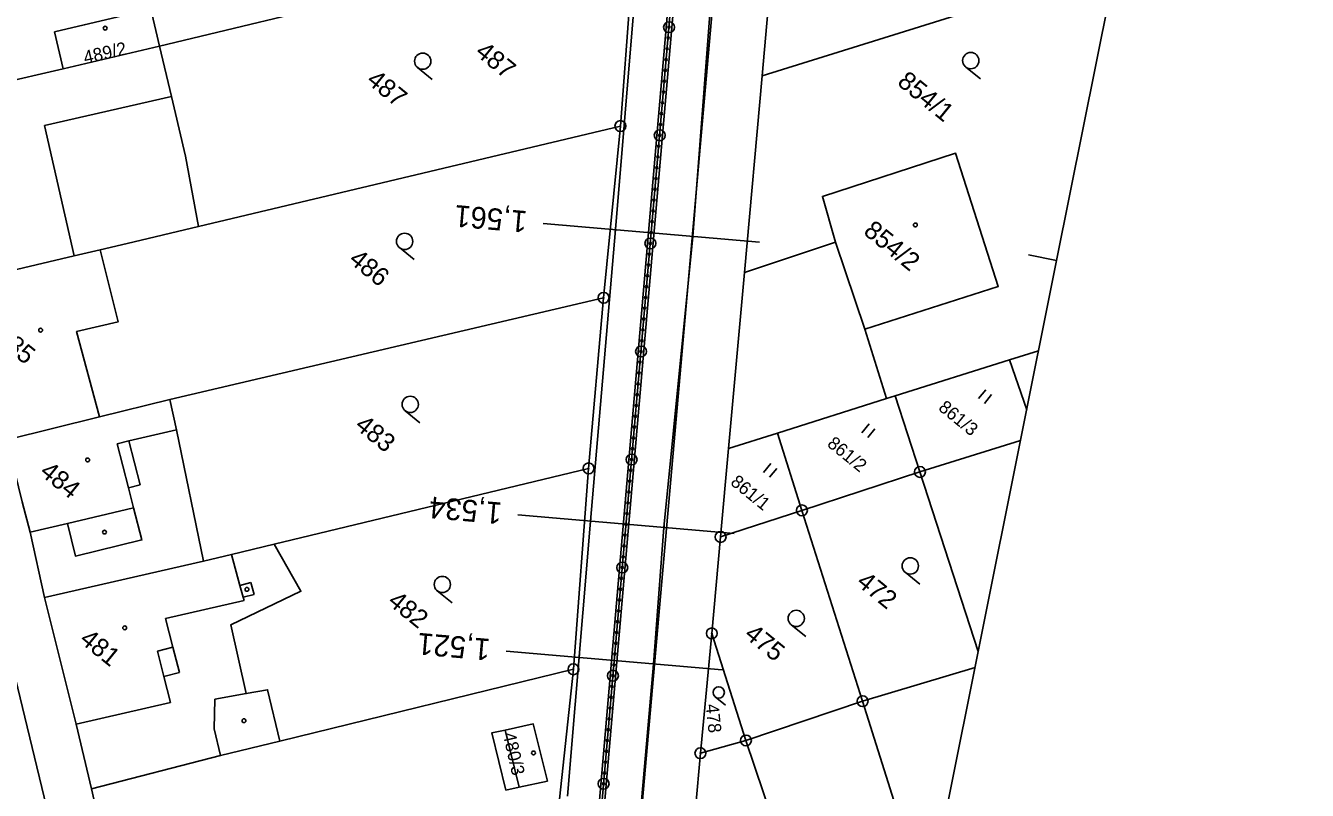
# Model space of a CAD drawing. Extents: x -548552 to -543113, y -1131925 to -1123599.
# Drawn here: x -547952.9 to -547834.8, y -1130256.8 to -1130186.3 of the extents above; entities that cross this region are included whole.
import ezdxf

# ---------------------------------------------------------------- set-up
doc = ezdxf.new("R2010")
doc.units = 0
for name, color, linetype in [('Hranice parcel', 7, 'Continuous'), ('Parcelní čísla', 7, 'Continuous'), ('Poz předměty', 7, 'Continuous'), ('Profile', 7, 'Continuous'), ('PROFILY', 7, 'Continuous'), ('STANIČENÍ', 7, 'Continuous'), ('STANIČENÍ PROFILY', 7, 'Continuous'), ('Vnitřní kresba', 7, 'Continuous'), ('Věcná břemena k části', 7, 'Continuous'), ('Značky bodu BP', 7, 'Continuous'), ('Značky budov', 7, 'Continuous'), ('Značky kultur', 7, 'Continuous')]:
    doc.layers.add(name, color=color, linetype=linetype)

msp = doc.modelspace()

# ---------------------------------------------------------------- linework, layer by layer
at = {"layer": 'Hranice parcel'}
for p, q in [((-547896.75, -1130177.64), (-547940.59, -1130188.23)), ((-547898.11, -1130195.58), (-547896.75, -1130177.64)), ((-547885.05, -1130190.95), (-547884.09, -1130180.24)), ((-547852.46, -1130180.78), (-547885.05, -1130190.95)), ((-547949.45, -1130190.3), (-547950.25, -1130186.89)), ((-547940.59, -1130188.23), (-547949.45, -1130190.3)), ((-547949.45, -1130190.3), (-547962.22, -1130193.28)), ((-547886.69, -1130209.09), (-547885.05, -1130190.95)), ((-547898.11, -1130195.58), (-547936.98, -1130204.83)), ((-547899.66, -1130211.41), (-547898.11, -1130195.58)), ((-547888.14, -1130225.31), (-547886.69, -1130209.09)), ((-547899.66, -1130211.41), (-547939.64, -1130220.79)), ((-547901.04, -1130227.14), (-547899.66, -1130211.41)), ((-547872.78, -1130220.46), (-547862.24, -1130217.13)), ((-547862.24, -1130217.13), (-547859.58, -1130216.29)), ((-547860.67, -1130221.75), (-547862.24, -1130217.13)), ((-547939.64, -1130220.79), (-547946.12, -1130222.39)), ((-547883.63, -1130223.89), (-547873.58, -1130220.71)), ((-547873.58, -1130220.71), (-547872.78, -1130220.46)), ((-547870.51, -1130227.47), (-547872.78, -1130220.46)), ((-547946.12, -1130222.39), (-547954.67, -1130224.5)), ((-547888.14, -1130225.31), (-547883.63, -1130223.89)), ((-547881.38, -1130231.01), (-547883.63, -1130223.89)), ((-547888.14, -1130225.31), (-547888.88, -1130233.46)), ((-547861.24, -1130224.58), (-547870.51, -1130227.47)), ((-547901.04, -1130227.14), (-547930.02, -1130234.13)), ((-547902.44, -1130245.66), (-547901.04, -1130227.14)), ((-547870.51, -1130227.47), (-547881.38, -1130231.01)), ((-547870.51, -1130227.47), (-547865.14, -1130244.03)), ((-547881.38, -1130231.01), (-547888.88, -1130233.46)), ((-547881.38, -1130231.01), (-547875.79, -1130248.6)), ((-547888.88, -1130233.46), (-547889.69, -1130242.35)), ((-547936.53, -1130235.68), (-547951.18, -1130239.03)), ((-547889.69, -1130242.35), (-547890.74, -1130253.39)), ((-547889.69, -1130242.35), (-547886.54, -1130252.22)), ((-547902.44, -1130245.66), (-547929.51, -1130252.29)), ((-547865.43, -1130245.49), (-547875.79, -1130248.6)), ((-547875.79, -1130248.6), (-547886.54, -1130252.22)), ((-547875.79, -1130248.6), (-547870.52, -1130265.27)), ((-547886.54, -1130252.22), (-547890.74, -1130253.39)), ((-547886.54, -1130252.22), (-547880.91, -1130269.02)), ((-547946.86, -1130256.68), (-547936.71, -1130300.6))]:
    msp.add_line(p, q, dxfattribs=at)
for points in [[(-547896.94, -1130267.49), (-547887.74, -1130163.39), (-547881.88, -1130098.3), (-547879.27, -1130068.76), (-547878.13, -1130056.89), (-547878.66, -1130053.71), (-547881.14, -1130041.82), (-547886.59, -1130027.64), (-547894.16, -1130014.15)], [(-547950.25, -1130186.89), (-547947.52, -1130186.26), (-547941.39, -1130184.82), (-547940.59, -1130188.23)], [(-547940.59, -1130188.23), (-547939.49, -1130192.87), (-547939.24, -1130193.91), (-547938.19, -1130198.36), (-547936.98, -1130204.83)], [(-547886.69, -1130209.09), (-547878.28, -1130206.28), (-547879.49, -1130202.06), (-547867.23, -1130198.09), (-547863.29, -1130210.38), (-547875.59, -1130214.31), (-547873.58, -1130220.71)], [(-547936.98, -1130204.83), (-547943.56, -1130206.4), (-547946.04, -1130206.98)], [(-547946.04, -1130206.98), (-547948.46, -1130207.55), (-547958.47, -1130209.9)], [(-547946.12, -1130222.39), (-547948.22, -1130214.53), (-547944.38, -1130213.62), (-547946.04, -1130206.98)], [(-547939.64, -1130220.79), (-547939.02, -1130223.57), (-547936.53, -1130235.68)], [(-547954.67, -1130224.5), (-547953.57, -1130228.83), (-547953.23, -1130230.21), (-547952.52, -1130233.02), (-547951.18, -1130239.03)], [(-547930.02, -1130234.13), (-547933.94, -1130235.09), (-547936.53, -1130235.68)], [(-547929.51, -1130252.29), (-547930.63, -1130247.55), (-547932.59, -1130247.9), (-547934.02, -1130241.56), (-547927.56, -1130238.46), (-547930.02, -1130234.13)], [(-547951.18, -1130239.03), (-547948.27, -1130250.73), (-547946.86, -1130256.68)], [(-547936.71, -1130300.6), (-547917.66, -1130284.08), (-547910.44, -1130275.7), (-547905.63, -1130267.65), (-547903.71, -1130257.64), (-547902.44, -1130245.66)], [(-547908.74, -1130251.26), (-547906.14, -1130250.7), (-547904.84, -1130255.97), (-547907.45, -1130256.53), (-547908.66, -1130256.79), (-547909.95, -1130251.51), (-547908.74, -1130251.26)], [(-547929.51, -1130252.29), (-547934.97, -1130253.6), (-547946.86, -1130256.68)], [(-547890.74, -1130253.39), (-547893.97, -1130289.11), (-547892.39, -1130291.55)]]:
    msp.add_lwpolyline(points, dxfattribs=at)
at = {"layer": 'Poz předměty'}
for p, q in [((-547900.31, -1130260.74), (-547883.44, -1130065.8)), ((-547899.81, -1130260.78), (-547882.94, -1130065.84)), ((-547896.31, -1130177.96), (-547898.56, -1130205.13)), ((-547891.45, -1130205.75), (-547889.36, -1130178.57)), ((-547898.56, -1130205.13), (-547900.86, -1130232.01)), ((-547894.1, -1130232.59), (-547891.45, -1130205.75)), ((-547900.86, -1130232.01), (-547902.99, -1130257.35)), ((-547894.1, -1130232.59), (-547895.07, -1130245.17)), ((-547895.07, -1130245.17), (-547896.46, -1130261.06))]:
    msp.add_line(p, q, dxfattribs=at)
at = {"layer": 'Profile'}
for p, q in [((-547834.8, -1130092.7), (-547857.91, -1130207.98)), ((-547857.91, -1130207.98), (-547881.02, -1130323.27)), ((-547857.91, -1130207.98), (-547860.5, -1130207.46))]:
    msp.add_line(p, q, dxfattribs=at)
at = {"layer": 'PROFILY'}
for points in [[(-547905.23, -1130204.56), (-547885.3, -1130206.28)], [(-547907.56, -1130231.43), (-547887.63, -1130233.15)], [(-547908.64, -1130244), (-547888.72, -1130245.72)]]:
    msp.add_lwpolyline(points, dxfattribs=at)
at = {"layer": 'STANIČENÍ'}
for p, q in [((-547900.06, -1130260.76), (-547883.19, -1130065.82)), ((-547898.58, -1130205.38), (-547898.52, -1130204.73)), ((-547891.5, -1130206.27), (-547891.43, -1130205.5)), ((-547900.89, -1130232.34), (-547900.84, -1130231.76)), ((-547894.11, -1130232.8), (-547894.08, -1130232.44)), ((-547901.95, -1130244.92), (-547901.89, -1130244.24)), ((-547895.1, -1130245.49), (-547895.04, -1130244.76))]:
    msp.add_line(p, q, dxfattribs=at)
for centre, radius in [((-547893.63, -1130186.47), 0.5), ((-547893.63, -1130186.47), 0.1), ((-547893.71, -1130187.47), 0.1), ((-547893.8, -1130188.46), 0.1), ((-547893.89, -1130189.46), 0.1), ((-547894.06, -1130191.45), 0.1), ((-547893.97, -1130190.45), 0.1), ((-547894.14, -1130192.45), 0.1), ((-547894.23, -1130193.44), 0.1), ((-547894.32, -1130194.44), 0.1), ((-547894.49, -1130196.43), 0.5), ((-547894.4, -1130195.44), 0.1), ((-547894.58, -1130197.43), 0.1), ((-547894.49, -1130196.43), 0.1), ((-547894.66, -1130198.42), 0.1), ((-547894.75, -1130199.42), 0.1), ((-547894.83, -1130200.42), 0.1), ((-547894.92, -1130201.41), 0.1), ((-547895.01, -1130202.41), 0.1), ((-547895.18, -1130204.4), 0.1), ((-547895.09, -1130203.41), 0.1), ((-547895.27, -1130205.4), 0.1), ((-547895.35, -1130206.4), 0.5), ((-547895.35, -1130206.4), 0.1), ((-547895.44, -1130207.39), 0.1), ((-547895.52, -1130208.39), 0.1), ((-547895.7, -1130210.38), 0.1), ((-547895.61, -1130209.38), 0.1), ((-547895.78, -1130211.38), 0.1), ((-547895.87, -1130212.37), 0.1), ((-547895.96, -1130213.37), 0.1), ((-547896.04, -1130214.37), 0.1), ((-547896.21, -1130216.36), 0.5), ((-547896.21, -1130216.36), 0.1), ((-547896.13, -1130215.36), 0.1), ((-547896.3, -1130217.35), 0.1), ((-547896.39, -1130218.35), 0.1), ((-547896.47, -1130219.35), 0.1), ((-547896.56, -1130220.34), 0.1), ((-547896.65, -1130221.34), 0.1), ((-547896.82, -1130223.33), 0.1), ((-547896.73, -1130222.34), 0.1), ((-547896.9, -1130224.33), 0.1), ((-547896.99, -1130225.32), 0.1), ((-547897.08, -1130226.32), 0.5), ((-547897.08, -1130226.32), 0.1), ((-547897.16, -1130227.32), 0.1), ((-547897.34, -1130229.31), 0.1), ((-547897.25, -1130228.31), 0.1), ((-547897.42, -1130230.31), 0.1), ((-547897.51, -1130231.3), 0.1), ((-547897.59, -1130232.3), 0.1), ((-547897.68, -1130233.29), 0.1), ((-547897.77, -1130234.29), 0.1), ((-547897.94, -1130236.28), 0.5), ((-547897.94, -1130236.28), 0.1), ((-547897.85, -1130235.29), 0.1), ((-547898.02, -1130237.28), 0.1), ((-547898.11, -1130238.28), 0.1), ((-547898.2, -1130239.27), 0.1), ((-547898.28, -1130240.27), 0.1), ((-547898.46, -1130242.26), 0.1), ((-547898.37, -1130241.26), 0.1), ((-547898.54, -1130243.26), 0.1), ((-547898.63, -1130244.25), 0.1), ((-547898.8, -1130246.25), 0.5), ((-547898.71, -1130245.25), 0.1), ((-547898.8, -1130246.25), 0.1), ((-547898.97, -1130248.24), 0.1), ((-547898.89, -1130247.24), 0.1), ((-547899.06, -1130249.24), 0.1), ((-547899.15, -1130250.23), 0.1), ((-547899.23, -1130251.23), 0.1), ((-547899.32, -1130252.22), 0.1), ((-547899.4, -1130253.22), 0.1), ((-547899.58, -1130255.21), 0.1), ((-547899.49, -1130254.22), 0.1), ((-547899.66, -1130256.21), 0.5), ((-547899.66, -1130256.21), 0.1)]:
    msp.add_circle(centre, radius, dxfattribs=at)
at = {"layer": 'Vnitřní kresba'}
for p, q in [((-547939.49, -1130192.87), (-547951.19, -1130195.54)), ((-547951.19, -1130195.54), (-547948.46, -1130207.55)), ((-547875.59, -1130214.31), (-547878.28, -1130206.28)), ((-547939.02, -1130223.57), (-547943.41, -1130224.61)), ((-547943.41, -1130224.61), (-547944.48, -1130224.86)), ((-547944.48, -1130224.86), (-547943.44, -1130228.93)), ((-547942.37, -1130228.65), (-547943.41, -1130224.61)), ((-547943.44, -1130228.93), (-547942.37, -1130228.65)), ((-547943.44, -1130228.93), (-547942.97, -1130230.77)), ((-547942.97, -1130230.77), (-547949.07, -1130232.21)), ((-547949.07, -1130232.21), (-547952.52, -1130233.02)), ((-547933.17, -1130237.92), (-547933.94, -1130235.09)), ((-547932.17, -1130237.66), (-547933.17, -1130237.92)), ((-547933.17, -1130237.92), (-547932.87, -1130239.02)), ((-547931.87, -1130238.75), (-547932.17, -1130237.66)), ((-547940.03, -1130240.99), (-547932.79, -1130239.33)), ((-547932.87, -1130239.02), (-547931.87, -1130238.75)), ((-547932.79, -1130239.33), (-547932.87, -1130239.02)), ((-547939.35, -1130243.63), (-547940.03, -1130240.99)), ((-547940.77, -1130244), (-547939.35, -1130243.63)), ((-547940.18, -1130246.32), (-547940.77, -1130244)), ((-547938.75, -1130245.95), (-547939.35, -1130243.63)), ((-547940.18, -1130246.32), (-547938.75, -1130245.95)), ((-547939.57, -1130248.71), (-547940.18, -1130246.32)), ((-547932.59, -1130247.9), (-547935.5, -1130248.42)), ((-547948.27, -1130250.73), (-547939.57, -1130248.71)), ((-547935.5, -1130248.42), (-547935.54, -1130251.14)), ((-547935.54, -1130251.14), (-547934.97, -1130253.6)), ((-547907.45, -1130256.53), (-547908.74, -1130251.26))]:
    msp.add_line(p, q, dxfattribs=at)
msp.add_lwpolyline([(-547942.97, -1130230.77), (-547942.2, -1130233.73), (-547948.34, -1130235.22), (-547949.07, -1130232.21)], dxfattribs=at)
at = {"layer": 'Věcná břemena k části'}
msp.add_lwpolyline([(-548000.27, -1130366.14), (-547970.93, -1130344.2), (-547968.69, -1130340.96), (-547974.59, -1130321.66), (-547959.54, -1130314.52), (-547943.27, -1130308.31), (-547941.93, -1130305.35), (-547939.71, -1130304.7), (-547938.06, -1130306.31), (-547934.94, -1130305.12), (-547938.08, -1130301.71), (-547937.18, -1130300.98), (-547944.79, -1130287.78), (-547944.77, -1130284.16), (-547966.35, -1130194.88), (-547973.4, -1130164.54), (-547974.96, -1130164.9), (-547975.83, -1130161.37), (-547977.47, -1130151.86), (-547976.4, -1130151.59), (-547979.82, -1130136.86), (-547987.06, -1130104.44), (-547987.66, -1130099.69)], dxfattribs=at)
at = {"layer": 'Značky bodu BP'}
for centre, radius in [((-547898.11, -1130195.58), 0.5), ((-547898.11, -1130195.58), 0.0303), ((-547899.66, -1130211.41), 0.5), ((-547899.66, -1130211.41), 0.0303), ((-547901.04, -1130227.14), 0.5), ((-547901.04, -1130227.14), 0.0303), ((-547870.51, -1130227.47), 0.5), ((-547870.51, -1130227.47), 0.0303), ((-547881.38, -1130231.01), 0.5), ((-547881.38, -1130231.01), 0.0303), ((-547888.88, -1130233.46), 0.5), ((-547888.88, -1130233.46), 0.0303), ((-547889.69, -1130242.35), 0.5), ((-547889.69, -1130242.35), 0.0303), ((-547902.44, -1130245.66), 0.5), ((-547902.44, -1130245.66), 0.0303), ((-547875.79, -1130248.6), 0.5), ((-547875.79, -1130248.6), 0.0303), ((-547886.54, -1130252.22), 0.5), ((-547886.54, -1130252.22), 0.0303), ((-547890.74, -1130253.39), 0.5), ((-547890.74, -1130253.39), 0.0303)]:
    msp.add_circle(centre, radius, dxfattribs=at)
at = {"layer": 'Značky budov'}
for centre in [(-547945.59, -1130186.56), (-547870.93, -1130204.7), (-547951.54, -1130214.4), (-547947.21, -1130226.36), (-547945.66, -1130233.01), (-547932.53, -1130238.29), (-547943.79, -1130241.83), (-547932.8, -1130250.4), (-547906.12, -1130253.37)]:
    msp.add_circle(centre, 0.175, dxfattribs=at)
at = {"layer": 'Značky kultur'}
for p, q in [((-547916.8, -1130190.18), (-547915.45, -1130191.29)), ((-547866.29, -1130190.14), (-547864.94, -1130191.24)), ((-547918.48, -1130206.79), (-547917.12, -1130207.89)), ((-547865.11, -1130220.71), (-547864.45, -1130219.9)), ((-547864.57, -1130221.15), (-547863.91, -1130220.34)), ((-547917.96, -1130221.83), (-547916.6, -1130222.93)), ((-547875.86, -1130223.85), (-547875.2, -1130223.03)), ((-547875.32, -1130224.29), (-547874.65, -1130223.48)), ((-547884.91, -1130227.52), (-547884.25, -1130226.7)), ((-547884.37, -1130227.96), (-547883.7, -1130227.14)), ((-547871.87, -1130236.71), (-547870.51, -1130237.81)), ((-547914.99, -1130238.42), (-547913.63, -1130239.52)), ((-547882.38, -1130241.55), (-547881.02, -1130242.65)), ((-547889.39, -1130248.2), (-547888.44, -1130248.97))]:
    msp.add_line(p, q, dxfattribs=at)
for centre, radius in [((-547916.33, -1130189.6), 0.75), ((-547865.82, -1130189.55), 0.75), ((-547918, -1130206.21), 0.75), ((-547917.48, -1130221.24), 0.75), ((-547871.4, -1130236.13), 0.75), ((-547914.52, -1130237.84), 0.75), ((-547881.91, -1130240.97), 0.75), ((-547889.05, -1130247.79), 0.525)]:
    msp.add_circle(centre, radius, dxfattribs=at)

# ---------------------------------------------------------------- texts
at = {"layer": 'Parcelní čísla'}
for s, height, rotation, p in [('489/2', 1.2, 12.8323, (-547947.44, -1130189.86)), ('487', 1.7, 320.8323, (-547911.59, -1130188.95)), ('487', 1.7, 320.8323, (-547921.61, -1130191.55)), ('854/1', 1.7, 320.8323, (-547872.69, -1130191.7)), ('854/2', 1.7, 320.8323, (-547875.81, -1130205.46)), ('486', 1.7, 320.8323, (-547923.24, -1130208.08)), ('485', 1.7, 320.8323, (-547955.86, -1130215.25)), ('861/3', 1.2, 320.8323, (-547868.89, -1130221.69)), ('483', 1.7, 320.8323, (-547922.68, -1130223.37)), ('861/2', 1.2, 320.8323, (-547879.14, -1130225.02)), ('484', 1.7, 320.8323, (-547951.72, -1130227.65)), ('861/1', 1.2, 320.8323, (-547888.05, -1130228.56)), ('472', 1.7, 320.8323, (-547876.45, -1130237.81)), ('482', 1.7, 320.8323, (-547919.65, -1130239.59)), ('475', 1.7, 320.8323, (-547886.79, -1130242.64)), ('481', 1.7, 320.8323, (-547948.05, -1130243.1)), ('478', 1.2, 275.8323, (-547890.25, -1130248.91)), ('480/3', 1.2, 282.8323, (-547908.96, -1130251.61))]:
    msp.add_text(s, height=height, rotation=rotation, dxfattribs=at).set_placement(p)
at = {"layer": 'STANIČENÍ PROFILY'}
for s, p in [('1,561', (-547906.64, -1130203.43)), ('1,534', (-547908.96, -1130230.3)), ('1,521', (-547910.05, -1130242.87))]:
    msp.add_text(s, height=2, rotation=175.0538, dxfattribs=at).set_placement(p)

doc.saveas('drawing.dxf')
